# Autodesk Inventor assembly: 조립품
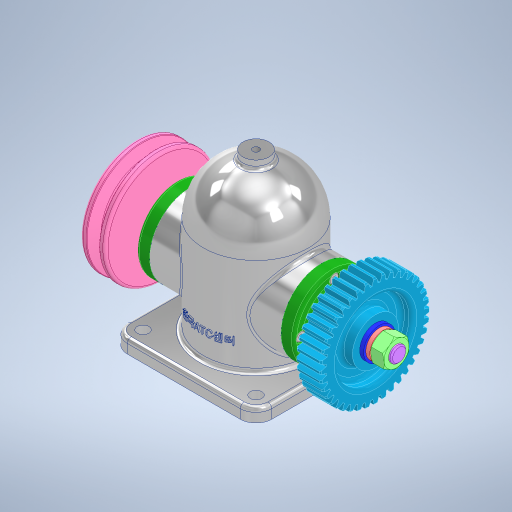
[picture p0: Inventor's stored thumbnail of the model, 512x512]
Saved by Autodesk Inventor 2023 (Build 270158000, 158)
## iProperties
Created: 2025-04
Part Number: 조립품
Document SubType Name: Assembly
Designer: Admin
Author: Admin
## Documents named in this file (14)
- C:\Users\Admin\Desktop\750406V1009\조립품.iam
- C:\Users\Admin\Desktop\750406V1009\본체.ipt
- C:\Users\Admin\Desktop\750406V1009\깊은 홈 볼 베어링 6203.ipt
- C:\Users\Admin\Desktop\750406V1009\축.ipt
- C:\Users\Admin\Desktop\750406V1009\커버.ipt
- C:\Users\Admin\Desktop\750406V1009\오일 실 26 38 8.ipt
- C:\Users\Admin\Desktop\750406V1009\6각 구멍붙이 볼트 M4x12.ipt
- C:\Users\Admin\Desktop\750406V1009\칼라.ipt
- C:\Users\Admin\Desktop\750406V1009\평행 키 5x5x12.ipt
- C:\Users\Admin\Desktop\750406V1009\스퍼기어.ipt
- C:\Users\Admin\Desktop\750406V1009\V 벨트 풀리.ipt
- C:\Users\Admin\Desktop\750406V1009\평와셔 M12.ipt
- C:\Users\Admin\Desktop\750406V1009\스프링 와셔 M12.ipt
- C:\Users\Admin\Desktop\750406V1009\6각 너트 M12x1.ipt
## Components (11 placed, 3 different names)
1. 6각 구멍붙이 볼트 M4x12:1
2. 6각 구멍붙이 볼트 M4x12:2
3. 6각 구멍붙이 볼트 M4x12:3
4. 6각 구멍붙이 볼트 M4x12:4
5. 6각 구멍붙이 볼트 M4x12:5
6. 6각 구멍붙이 볼트 M4x12:6
7. 6각 구멍붙이 볼트 M4x12:7
8. 6각 구멍붙이 볼트 M4x12:8
9. V 벨트 풀리:1
10. 6각 너트 M12x1:1
11. 6각 너트 M12x1:2
